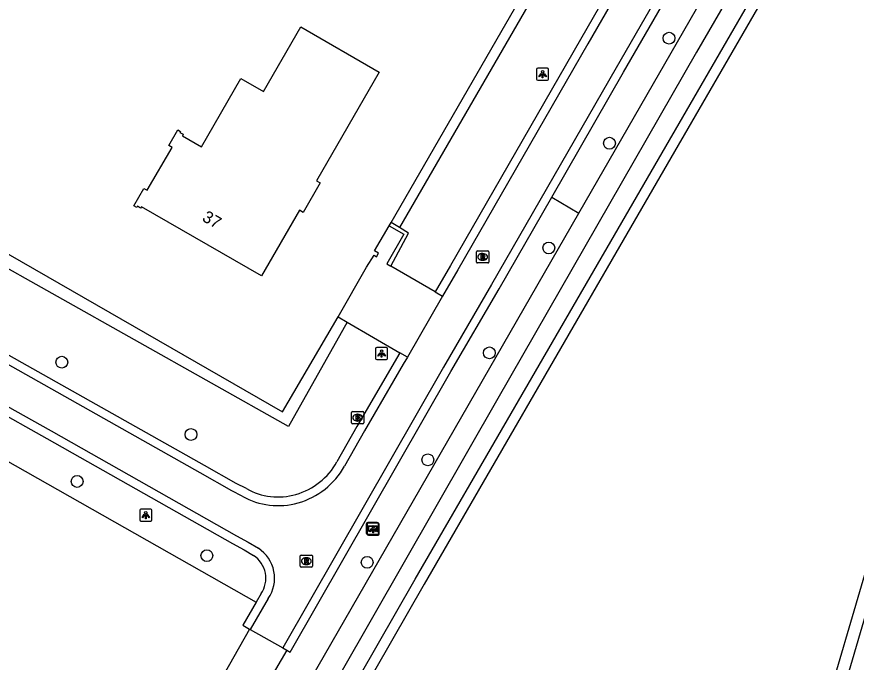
# Model space of a CAD drawing. Extents: x 156502 to 159074, y 384229 to 386094.
# Drawn here: x 157237.7 to 157307.2, y 385633.7 to 385687.2 of the extents above; entities that cross this region are included whole.
import ezdxf

# ---------------------------------------------------------------- set-up
doc = ezdxf.new("R2010")
doc.units = 0
for name, color, linetype in [('IMGEO_Boom', 7, 'Continuous'), ('IMGEO_Brandkraan', 7, 'Continuous'), ('IMGEO_Gemengd_bos', 7, 'Continuous'), ('IMGEO_Grasland_agrarisch', 7, 'Continuous'), ('IMGEO_Greppel_droge_sloot', 7, 'Continuous'), ('IMGEO_Groenvoorziening', 7, 'Continuous'), ('IMGEO_Haag', 7, 'Continuous'), ('IMGEO_Hek', 7, 'Continuous'), ('IMGEO_Lichtpunt', 7, 'Continuous'), ('IMGEO_Pand', 7, 'Continuous'), ('IMGEO_Pand_nummerreeks', 7, 'Continuous'), ('IMGEO_Rijbaan_lokaal_gesloten', 7, 'Continuous'), ('IMGEO_Rijbaan_lokaal_halfverhard', 7, 'Continuous'), ('IMGEO_Rijbaan_lokaal_open', 7, 'Continuous'), ('IMGEO_Rioolput', 7, 'Continuous'), ('IMGEO_Verklikker', 7, 'Continuous'), ('IMGEO_Waterloop', 7, 'Continuous')]:
    doc.layers.add(name, color=color, linetype=linetype)

msp = doc.modelspace()

# ---------------------------------------------------------------- linework, layer by layer
at = {"layer": 'IMGEO_Boom'}
for centre in [(157291.666, 385685.381), (157286.735, 385676.689), (157281.714, 385668.026), (157276.8, 385659.34), (157241.417, 385658.57), (157252.104, 385652.586), (157271.704, 385650.491), (157242.683, 385648.703), (157253.419, 385642.561), (157266.683, 385642.007)]:
    msp.add_circle(centre, 0.489, dxfattribs=at)
at = {"layer": 'IMGEO_Brandkraan'}
for p, q in [((157265.469, 385654.479), (157266.321, 385654.479)), ((157265.394, 385653.553), (157265.394, 385654.405)), ((157265.882, 385654.259), (157265.907, 385654.259)), ((157266.395, 385654.405), (157266.395, 385653.553)), ((157266.321, 385653.479), (157265.469, 385653.479)), ((157265.905, 385653.699), (157265.88, 385653.699))]:
    msp.add_line(p, q, dxfattribs=at)
for points in [[(157265.469, 385654.479), (157266.321, 385654.479)], [(157265.394, 385653.553), (157265.394, 385654.405)], [(157265.742, 385654.179), (157265.742, 385653.779), (157265.955, 385653.779)], [(157265.973, 385654.179), (157265.742, 385654.179)], [(157265.921, 385654.098), (157265.867, 385654.098), (157265.867, 385654.022)], [(157265.867, 385654.022), (157265.92, 385654.022)], [(157265.929, 385653.946), (157265.867, 385653.946), (157265.867, 385653.865)], [(157265.867, 385653.865), (157265.929, 385653.865)], [(157266.395, 385654.405), (157266.395, 385653.553)], [(157266.321, 385653.479), (157265.469, 385653.479)]]:
    msp.add_lwpolyline(points, dxfattribs=at)
for centre, radius, start, end in [((157265.471, 385654.403), 0.0765, 91.55205, 178.44795), ((157265.471, 385654.403), 0.0765, 91.55205, 178.44795), ((157266.319, 385654.403), 0.0765, 1.55205, 88.44795), ((157266.319, 385654.403), 0.0765, 1.55205, 88.44795), ((157265.922, 385654.06), 0.0379, 267.82845, 90.93552), ((157265.93, 385653.905), 0.0404, 269.87594, 90.50774), ((157265.961, 385654.03), 0.251, 268.66757, 293.53466), ((157265.977, 385654.034), 0.145, 59.4692, 91.53667), ((157266.002, 385654.081), 0.0922, 285.51372, 58.15012), ((157266.007, 385653.889), 0.105, 301.31148, 78.98903), ((157265.471, 385653.555), 0.0765, 181.55205, 268.44795), ((157265.471, 385653.555), 0.0765, 181.55205, 268.44795), ((157266.319, 385653.555), 0.0765, 271.55205, 358.44795), ((157266.319, 385653.555), 0.0765, 271.55205, 358.44795)]:
    msp.add_arc(centre, radius, start, end, dxfattribs=at)
for centre, major_axis, ratio, start_param, end_param in [((157265.881, 385653.979), (-0.387, 0.002), 0.722429, 4.712389, 7.853982), ((157265.906, 385653.979), (-0.39, 0.002), 0.717154, 1.570796, 4.712389)]:
    msp.add_ellipse(centre, major_axis=major_axis, ratio=ratio, start_param=start_param, end_param=end_param, dxfattribs=at)
at = {"layer": 'IMGEO_Gemengd_bos'}
msp.add_lwpolyline([(157395.472, 385857.325), (157372.587, 385816.736), (157334.959, 385750), (157287.88, 385668.677), (157271.388, 385640.19), (157191.031, 385500), (157152.554, 385432.884), (157150.665, 385429.588), (157146.166, 385421.741)], dxfattribs=at)
at = {"layer": 'IMGEO_Grasland_agrarisch'}
msp.add_lwpolyline([(157162.655, 385699.661), (157194.774, 385674.261), (157257.492, 385638.709)], dxfattribs=at)
at = {"layer": 'IMGEO_Greppel_droge_sloot'}
for points in [[(157393.364, 385858.054), (157393.108, 385857.612), (157362.753, 385804.111), (157325.818, 385739.168), (157293.922, 385684.217), (157277.506, 385655.557), (157259.264, 385623.708), (157238.621, 385587.751), (157224.85, 385563.789), (157203.074, 385525.899), (157174.272, 385475.365), (157161.248, 385452.051), (157151.078, 385433.934), (157146.7, 385427.265), (157144.863, 385424.97)], [(157146.463, 385424.365), (157148.979, 385428.052), (157150.577, 385430.986), (157151.892, 385433.401), (157190.309, 385500.414), (157270.667, 385640.605), (157287.16, 385669.094), (157334.237, 385750.413), (157371.862, 385817.145), (157394.598, 385857.47)]]:
    msp.add_lwpolyline(points, dxfattribs=at)
at = {"layer": 'IMGEO_Groenvoorziening'}
for points in [[(157284.199, 385670.89), (157329.731, 385750), (157392.248, 385858.973)], [(157268.668, 385670.142), (157291.965, 385710.53)], [(157291.965, 385710.53), (157292.73, 385710.099), (157269.35, 385669.721)], [(157228.873, 385672.175), (157259.687, 385654.464), (157264.272, 385662.327)], [(157281.966, 385672.234), (157284.199, 385670.89)], [(157265.028, 385661.886), (157260.161, 385653.244), (157228.279, 385671.171)], [(157172.104, 385476.13), (157284.199, 385670.89)]]:
    msp.add_lwpolyline(points, dxfattribs=at)
at = {"layer": 'IMGEO_Haag'}
for points in [[(157268.496, 385669.844), (157268.668, 385670.142)], [(157269.35, 385669.721), (157268.668, 385670.142)], [(157268.645, 385666.521), (157270.11, 385669.253), (157269.35, 385669.721)]]:
    msp.add_lwpolyline(points, dxfattribs=at)
at = {"layer": 'IMGEO_Hek'}
for points in [[(157334.959, 385750), (157287.88, 385668.677)], [(157287.88, 385668.677), (157271.388, 385640.19), (157191.031, 385500)]]:
    msp.add_lwpolyline(points, dxfattribs=at)
at = {"layer": 'IMGEO_Lichtpunt'}
for p, q in [((157280.699, 385682.798), (157280.699, 385681.991)), ((157280.699, 385682.798), (157280.699, 385681.991)), ((157281.601, 385682.893), (157280.793, 385682.893)), ((157281.601, 385682.893), (157280.793, 385682.893)), ((157281.695, 385681.991), (157281.695, 385682.798)), ((157281.695, 385681.991), (157281.695, 385682.798)), ((157280.793, 385681.897), (157281.601, 385681.897)), ((157280.793, 385681.897), (157281.601, 385681.897)), ((157267.38, 385659.688), (157267.38, 385658.881)), ((157267.38, 385659.688), (157267.38, 385658.881)), ((157268.282, 385659.783), (157267.474, 385659.783)), ((157268.282, 385659.783), (157267.474, 385659.783)), ((157268.376, 385658.881), (157268.376, 385659.688)), ((157268.376, 385658.881), (157268.376, 385659.688)), ((157267.474, 385658.787), (157268.282, 385658.787)), ((157267.474, 385658.787), (157268.282, 385658.787)), ((157247.868, 385646.324), (157247.868, 385645.517)), ((157247.868, 385646.324), (157247.868, 385645.517)), ((157248.77, 385646.419), (157247.962, 385646.419)), ((157248.77, 385646.419), (157247.962, 385646.419)), ((157248.864, 385645.517), (157248.864, 385646.324)), ((157248.864, 385645.517), (157248.864, 385646.324)), ((157247.962, 385645.423), (157248.77, 385645.423)), ((157247.962, 385645.423), (157248.77, 385645.423)), ((157266.69, 385645.158), (157266.69, 385644.351)), ((157266.69, 385645.158), (157266.69, 385644.351)), ((157267.592, 385645.253), (157266.784, 385645.253)), ((157267.592, 385645.253), (157266.784, 385645.253)), ((157267.686, 385644.351), (157267.686, 385645.158)), ((157267.686, 385644.351), (157267.686, 385645.158)), ((157266.784, 385644.257), (157267.592, 385644.257)), ((157266.784, 385644.257), (157267.592, 385644.257))]:
    msp.add_line(p, q, dxfattribs=at)
for points in [[(157281.073, 385682.462), (157281.112, 385682.434), (157280.924, 385682.172), (157280.886, 385682.199), (157281.073, 385682.462)], [(157281.175, 385682.414), (157281.222, 385682.414), (157281.222, 385682.092), (157281.175, 385682.092), (157281.175, 385682.414)], [(157281.285, 385682.434), (157281.323, 385682.461), (157281.51, 385682.199), (157281.471, 385682.171), (157281.285, 385682.434)], [(157267.754, 385659.352), (157267.793, 385659.324), (157267.605, 385659.062), (157267.567, 385659.089), (157267.754, 385659.352)], [(157267.966, 385659.324), (157268.004, 385659.351), (157268.191, 385659.089), (157268.152, 385659.061), (157267.966, 385659.324)], [(157267.856, 385659.304), (157267.903, 385659.304), (157267.903, 385658.982), (157267.856, 385658.982), (157267.856, 385659.304)], [(157248.242, 385645.988), (157248.281, 385645.96), (157248.093, 385645.698), (157248.055, 385645.725), (157248.242, 385645.988)], [(157248.344, 385645.94), (157248.391, 385645.94), (157248.391, 385645.618), (157248.344, 385645.618), (157248.344, 385645.94)], [(157248.454, 385645.96), (157248.492, 385645.987), (157248.679, 385645.725), (157248.64, 385645.697), (157248.454, 385645.96)], [(157267.064, 385644.822), (157267.103, 385644.794), (157266.915, 385644.532), (157266.877, 385644.559), (157267.064, 385644.822)], [(157267.166, 385644.774), (157267.213, 385644.774), (157267.213, 385644.452), (157267.166, 385644.452), (157267.166, 385644.774)], [(157267.276, 385644.794), (157267.314, 385644.821), (157267.501, 385644.559), (157267.462, 385644.531), (157267.276, 385644.794)]]:
    msp.add_lwpolyline(points, dxfattribs=at)
for centre in [(157281.198, 385682.596), (157267.879, 385659.486), (157248.367, 385646.122), (157267.189, 385644.956)]:
    msp.add_circle(centre, 0.0994, dxfattribs=at)
for centre, start, end in [((157280.793, 385682.798), 90, 180), ((157280.793, 385682.798), 90, 180), ((157281.601, 385682.798), 0, 90), ((157281.601, 385682.798), 0, 90), ((157280.793, 385681.991), 180, 270), ((157280.793, 385681.991), 180, 270), ((157281.601, 385681.991), 270, 0), ((157281.601, 385681.991), 270, 360), ((157267.474, 385659.688), 90, 180), ((157267.474, 385659.688), 90, 180), ((157268.282, 385659.688), 0, 90), ((157268.282, 385659.688), 0, 90), ((157267.474, 385658.881), 180, 270), ((157267.474, 385658.881), 180, 270), ((157268.282, 385658.881), 270, 0), ((157268.282, 385658.881), 270, 360), ((157247.962, 385646.324), 90, 180), ((157247.962, 385646.324), 90, 180), ((157248.77, 385646.324), 0, 90), ((157248.77, 385646.324), 0, 90), ((157247.962, 385645.517), 180, 270), ((157247.962, 385645.517), 180, 270), ((157248.77, 385645.517), 270, 0), ((157248.77, 385645.517), 270, 360), ((157266.784, 385645.158), 90, 180), ((157266.784, 385645.158), 90, 180), ((157267.592, 385645.158), 0, 90), ((157267.592, 385645.158), 0, 90), ((157266.784, 385644.351), 180, 270), ((157266.784, 385644.351), 180, 270), ((157267.592, 385644.351), 270, 0), ((157267.592, 385644.351), 270, 360)]:
    msp.add_arc(centre, 0.0946, start, end, dxfattribs=at)
at = {"layer": 'IMGEO_Pand'}
msp.add_lwpolyline([(157250.543, 385676.331), (157250.263, 385676.494), (157251.022, 385677.8), (157251.245, 385677.671), (157251.195, 385677.584), (157251.463, 385677.429), (157251.391, 385677.304), (157252.962, 385676.397), (157256.222, 385682.047), (157258.098, 385680.966), (157261.183, 385686.32), (157267.678, 385682.565), (157262.487, 385673.585), (157262.801, 385673.405), (157261.401, 385670.966), (157261.08, 385671.15), (157257.932, 385665.706), (157248.01, 385671.435), (157247.94, 385671.315), (157247.671, 385671.47), (157247.611, 385671.366), (157247.366, 385671.507), (157248.205, 385672.951), (157248.48, 385672.792), (157250.543, 385676.331)], dxfattribs=at)
at = {"layer": 'IMGEO_Rijbaan_lokaal_gesloten'}
for points in [[(157256.958, 385636.487), (157178.241, 385497.482), (157173.759, 385489.447), (157172.284, 385487.327)], [(157256.958, 385636.487), (157257.007, 385636.458)], [(157257.007, 385636.458), (157259.699, 385634.92)], [(157260.023, 385634.734), (157258.636, 385632.327), (157175.427, 385485.533)], [(157259.699, 385634.92), (157260.023, 385634.734)]]:
    msp.add_lwpolyline(points, dxfattribs=at)
at = {"layer": 'IMGEO_Rijbaan_lokaal_halfverhard'}
for points in [[(157281.966, 385672.234), (157287.901, 385682.571), (157297.811, 385699.744), (157305.606, 385713.266), (157310.603, 385721.93), (157349.521, 385789.087)], [(157297.663, 385708.443), (157293.657, 385701.479), (157284.326, 385685.265), (157273.57, 385666.582), (157272.301, 385664.385)], [(157196.397, 385676.905), (157226.319, 385660.026), (157240.175, 385652.256), (157255.54, 385643.568), (157256.495, 385643.049), (157257.289, 385642.569)], [(157260.023, 385634.734), (157260.323, 385634.562), (157273.616, 385657.789), (157277.603, 385664.635), (157281.966, 385672.234)], [(157256.698, 385648.11), (157255.851, 385648.542), (157253.232, 385650.034), (157236.616, 385659.381), (157225.122, 385665.836)], [(157269.39, 385659.346), (157265.836, 385653.246), (157264.179, 385650.319)], [(157257.907, 385639.417), (157257.492, 385638.709)], [(157257.492, 385638.709), (157256.386, 385636.821), (157256.958, 385636.487)]]:
    msp.add_lwpolyline(points, dxfattribs=at)
for centre, radius, start, end in [((157259.258, 385653.035), 5.621, 285.73079, 331.10175), ((157259.32, 385652.748), 5.328, 240.52423, 285.93076), ((157256.055, 385640.69), 2.248, 325.48576, 56.70031)]:
    msp.add_arc(centre, radius, start, end, dxfattribs=at)
at = {"layer": 'IMGEO_Rijbaan_lokaal_open'}
for points in [[(157348.91, 385789.439), (157309.98, 385722.29), (157304.982, 385713.626), (157297.187, 385700.104), (157287.277, 385682.931), (157276.979, 385664.993), (157272.994, 385658.151), (157259.699, 385634.92)], [(157298.287, 385708.085), (157294.281, 385701.12), (157284.95, 385684.906), (157274.194, 385666.223), (157272.923, 385664.022)], [(157256.344, 385647.483), (157255.495, 385647.916), (157252.876, 385649.408), (157236.263, 385658.753), (157223.934, 385665.69), (157198.978, 385679.748)], [(157196.751, 385677.532), (157226.671, 385660.654), (157240.529, 385652.883), (157255.884, 385644.201), (157256.839, 385643.682), (157257.684, 385643.171)], [(157264.272, 385662.327), (157266.64, 385666.428), (157267.252, 385667.419), (157267.448, 385667.3), (157267.622, 385667.589), (157267.294, 385667.793), (157268.496, 385669.844)], [(157268.496, 385669.844), (157269.709, 385669.16), (157268.307, 385666.718), (157268.645, 385666.521)], [(157272.301, 385664.385), (157268.645, 385666.521)], [(157272.301, 385664.385), (157272.923, 385664.022)], [(157272.923, 385664.022), (157270.012, 385658.984)], [(157264.272, 385662.327), (157265.028, 385661.886)], [(157265.028, 385661.886), (157269.39, 385659.346)], [(157270.012, 385658.984), (157269.39, 385659.346)], [(157270.012, 385658.984), (157269.674, 385658.399), (157266.458, 385652.883), (157264.806, 385649.964)], [(157258.5, 385639.009), (157257.007, 385636.458)]]:
    msp.add_lwpolyline(points, dxfattribs=at)
for centre, radius, start, end in [((157259.254, 385653.042), 6.348, 285.749, 330.999), ((157259.32, 385652.749), 6.048, 240.5313, 285.90411), ((157256.054, 385640.69), 2.968, 325.49651, 56.68886)]:
    msp.add_arc(centre, radius, start, end, dxfattribs=at)
at = {"layer": 'IMGEO_Rioolput'}
for p, q in [((157275.74, 385666.854), (157275.74, 385667.706)), ((157275.815, 385667.78), (157276.667, 385667.78)), ((157276.741, 385667.706), (157276.741, 385666.854)), ((157276.251, 385667), (157276.226, 385667)), ((157276.228, 385667.56), (157276.253, 385667.56)), ((157276.667, 385666.78), (157275.815, 385666.78)), ((157261.149, 385641.683), (157261.149, 385642.535)), ((157261.224, 385642.609), (157262.076, 385642.609)), ((157261.637, 385642.389), (157261.662, 385642.389)), ((157262.15, 385642.535), (157262.15, 385641.683)), ((157262.076, 385641.609), (157261.224, 385641.609)), ((157261.66, 385641.829), (157261.635, 385641.829))]:
    msp.add_line(p, q, dxfattribs=at)
for points in [[(157275.74, 385666.854), (157275.74, 385667.706)], [(157275.815, 385667.78), (157276.667, 385667.78)], [(157276.741, 385667.706), (157276.741, 385666.854)], [(157276.329, 385667.478), (157276.077, 385667.48), (157276.077, 385667.08)], [(157276.077, 385667.08), (157276.201, 385667.08), (157276.201, 385667.242), (157276.212, 385667.242)], [(157276.255, 385667.399), (157276.201, 385667.399), (157276.201, 385667.318)], [(157276.201, 385667.318), (157276.253, 385667.318)], [(157276.259, 385667.213), (157276.33, 385667.08), (157276.47, 385667.08), (157276.405, 385667.206)], [(157276.667, 385666.78), (157275.815, 385666.78)], [(157261.149, 385641.683), (157261.149, 385642.535)], [(157261.224, 385642.609), (157262.076, 385642.609)], [(157261.738, 385642.307), (157261.486, 385642.309), (157261.486, 385641.909)], [(157261.486, 385641.909), (157261.61, 385641.909), (157261.61, 385642.071), (157261.621, 385642.071)], [(157261.664, 385642.228), (157261.61, 385642.228), (157261.61, 385642.147)], [(157261.61, 385642.147), (157261.662, 385642.147)], [(157261.668, 385642.042), (157261.739, 385641.909), (157261.879, 385641.909), (157261.814, 385642.035)], [(157262.15, 385642.535), (157262.15, 385641.683)], [(157262.076, 385641.609), (157261.224, 385641.609)]]:
    msp.add_lwpolyline(points, dxfattribs=at)
for centre, radius, start, end in [((157275.817, 385667.704), 0.0765, 91.55205, 178.44795), ((157275.817, 385667.704), 0.0765, 91.55205, 178.44795), ((157276.665, 385667.704), 0.0765, 1.55205, 88.44795), ((157276.665, 385667.704), 0.0765, 1.55205, 88.44795), ((157276.211, 385667.189), 0.0533, 26.02933, 88.69889), ((157276.237, 385667.507), 0.19, 274.7715, 282.96867), ((157276.261, 385667.303), 0.0964, 77.00612, 93.18647), ((157276.275, 385667.36), 0.0378, 276.66336, 79.67722), ((157276.328, 385667.368), 0.109, 350.36119, 89.41601), ((157276.326, 385667.368), 0.112, 277.58423, 350.98172), ((157276.31, 385667.153), 0.108, 29.51342, 73.79051), ((157275.817, 385666.856), 0.0765, 181.55205, 268.44795), ((157275.817, 385666.856), 0.0765, 181.55205, 268.44795), ((157276.665, 385666.856), 0.0765, 271.55205, 358.44795), ((157276.665, 385666.856), 0.0765, 271.55205, 358.44795), ((157261.226, 385642.533), 0.0765, 91.55205, 178.44795), ((157261.226, 385642.533), 0.0765, 91.55205, 178.44795), ((157261.62, 385642.018), 0.0533, 26.02933, 88.69889), ((157261.646, 385642.336), 0.19, 274.7715, 282.96867), ((157261.67, 385642.132), 0.0964, 77.00612, 93.18647), ((157261.684, 385642.189), 0.0378, 276.66336, 79.67722), ((157261.737, 385642.197), 0.109, 350.36119, 89.41601), ((157261.735, 385642.197), 0.112, 277.58423, 350.98172), ((157261.719, 385641.982), 0.108, 29.51342, 73.79051), ((157262.074, 385642.533), 0.0765, 1.55205, 88.44795), ((157262.074, 385642.533), 0.0765, 1.55205, 88.44795), ((157261.226, 385641.685), 0.0765, 181.55205, 268.44795), ((157261.226, 385641.685), 0.0765, 181.55205, 268.44795), ((157262.074, 385641.685), 0.0765, 271.55205, 358.44795), ((157262.074, 385641.685), 0.0765, 271.55205, 358.44795)]:
    msp.add_arc(centre, radius, start, end, dxfattribs=at)
for centre, major_axis, ratio, start_param, end_param in [((157276.227, 385667.28), (-0.387, 0.002), 0.722429, 4.712389, 7.853982), ((157276.252, 385667.28), (-0.39, 0.002), 0.717154, 1.570796, 4.712389), ((157261.636, 385642.109), (-0.387, 0.002), 0.722429, 4.712389, 7.853982), ((157261.661, 385642.109), (-0.39, 0.002), 0.717154, 1.570796, 4.712389)]:
    msp.add_ellipse(centre, major_axis=major_axis, ratio=ratio, start_param=start_param, end_param=end_param, dxfattribs=at)
at = {"layer": 'IMGEO_Verklikker'}
for p, q in [((157266.627, 385644.406), (157266.627, 385645.206)), ((157266.627, 385645.206), (157266.627, 385644.406)), ((157266.727, 385645.306), (157267.517, 385645.306)), ((157267.517, 385645.306), (157266.727, 385645.306)), ((157267.617, 385645.206), (157267.617, 385644.406)), ((157267.617, 385644.406), (157267.617, 385645.206)), ((157267.517, 385644.306), (157266.727, 385644.306)), ((157266.727, 385644.306), (157267.517, 385644.306))]:
    msp.add_line(p, q, dxfattribs=at)
for points in [[(157266.728, 385645.038), (157267.516, 385645.038), (157267.516, 385644.574), (157266.728, 385644.574), (157266.728, 385645.038)], [(157266.793, 385644.973), (157266.793, 385644.639), (157267.451, 385644.639), (157267.451, 385644.973), (157266.793, 385644.973)]]:
    msp.add_lwpolyline(points, dxfattribs=at)
for centre, start, end in [((157266.727, 385645.206), 90, 180), ((157266.727, 385645.206), 90, 180), ((157267.517, 385645.206), 0, 90), ((157267.517, 385645.206), 360, 90), ((157266.727, 385644.406), 180, 270), ((157266.727, 385644.406), 180, 270), ((157267.517, 385644.406), 270, 0), ((157267.517, 385644.406), 270, 0)]:
    msp.add_arc(centre, 0.1, start, end, dxfattribs=at)
at = {"layer": 'IMGEO_Waterloop'}
for points in [[(157474.535, 385779.541), (157465.955, 385777.559), (157451.382, 385773.862), (157437.07, 385769.662), (157425.911, 385765.178), (157414.974, 385759.352), (157403.774, 385752.429), (157400.133, 385750), (157384.736, 385739.727), (157369.609, 385728.709), (157360.183, 385720.315), (157351.569, 385711.908), (157343.546, 385703.103), (157337.152, 385695.719), (157330.577, 385686.886), (157327.248, 385681.808), (157320.323, 385669.007), (157314.813, 385656.812), (157309.551, 385643.224), (157304.761, 385626.849), (157289.943, 385563.143), (157287.022, 385552.687)], [(157286.05, 385552.958), (157288.965, 385563.393), (157303.785, 385627.105), (157308.595, 385643.548), (157313.882, 385657.202)]]:
    msp.add_lwpolyline(points, dxfattribs=at)

# ---------------------------------------------------------------- texts
at = {"layer": 'IMGEO_Pand_nummerreeks'}
msp.add_text('37', height=1, rotation=329.99993, dxfattribs=at).set_placement((157252.958, 385670.31))

doc.saveas('drawing.dxf')
